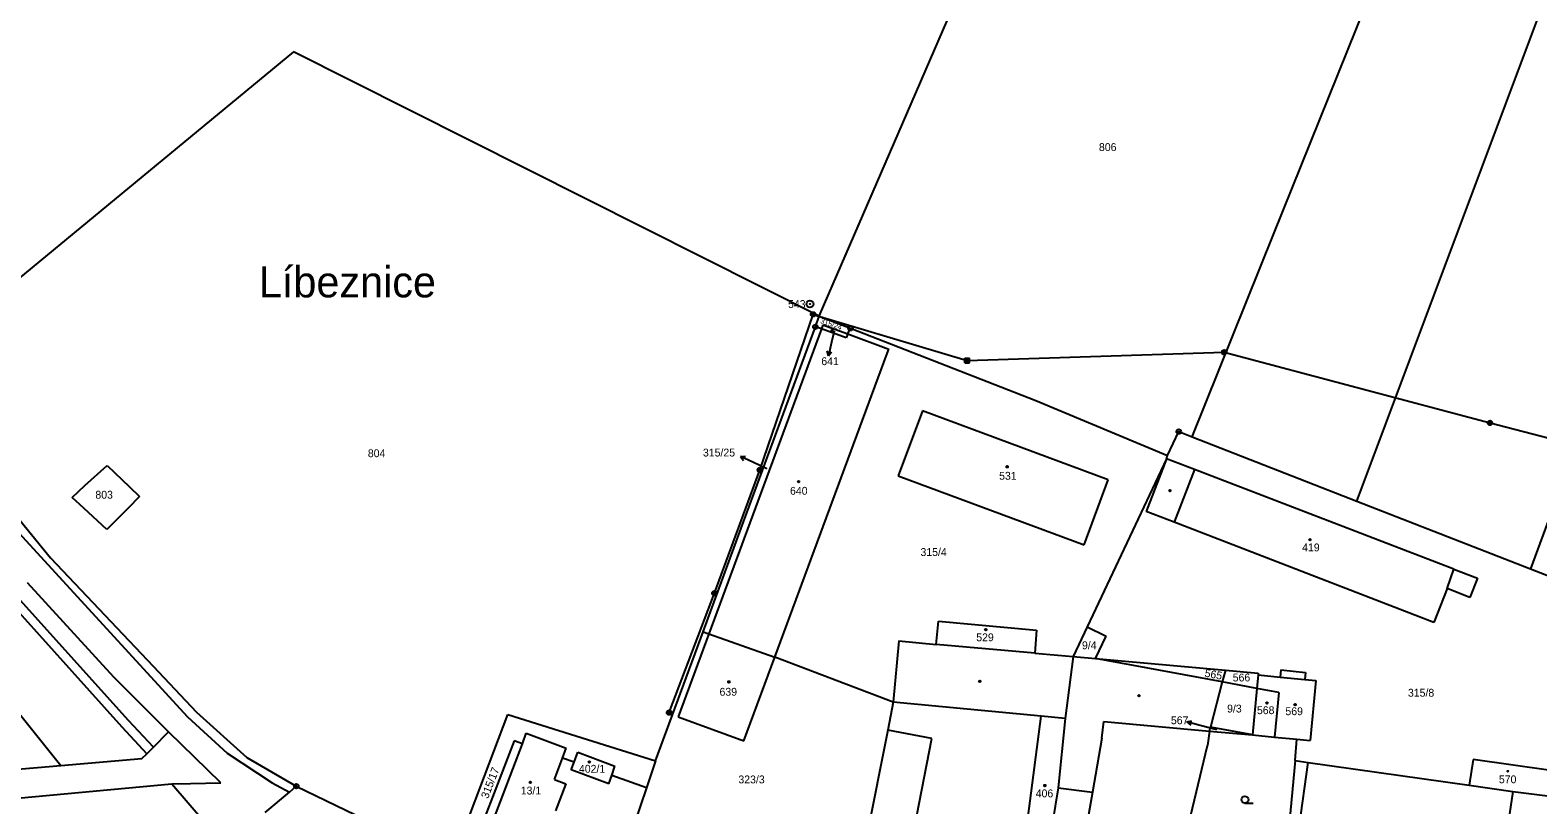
# Model space of a CAD drawing. Extents: x -738131 to -734179, y -1033447 to -1030078.
# Drawn here: x -736374.8 to -736048.4, y -1031856.8 to -1031689.1 of the extents above; entities that cross this region are included whole.
import ezdxf

# ---------------------------------------------------------------- set-up
doc = ezdxf.new("R2010")
doc.units = 0
for name, color, linetype in [('Vrstva 1', 7, 'Continuous'), ('Vrstva 2', 7, 'Continuous'), ('Vrstva 3', 7, 'Continuous'), ('Vrstva 4', 7, 'Continuous'), ('Vrstva 5', 7, 'Continuous'), ('Vrstva 6', 7, 'Continuous'), ('Vrstva 7', 7, 'Continuous'), ('Vrstva 8', 7, 'Continuous')]:
    doc.layers.add(name, color=color, linetype=linetype)

msp = doc.modelspace()

# ---------------------------------------------------------------- linework, layer by layer
at = {"layer": 'Vrstva 1'}
for points in [[(-736181.96, -1031700.18), (-736159.97, -1031649.35)], [(-736087.54, -1031791.01), (-736034.3, -1031649.01)], [(-736105.57, -1031733.34), (-736083.6, -1031678.63)], [(-736317.82, -1031693.78), (-736392.24, -1031755.11)], [(-736203.95, -1031750.98), (-736317.82, -1031693.78)], [(-736203.95, -1031750.98), (-736181.96, -1031700.18)], [(-736017.61, -1031718), (-736049.93, -1031805.67)], [(-736123.18, -1031777.12), (-736105.57, -1031733.34)], [(-736204.8, -1031753.3), (-736203.95, -1031750.98)], [(-736203.95, -1031750.98), (-736197.18, -1031753.62)], [(-736203.49, -1031753.77), (-736227.87, -1031819.76)], [(-736220.85, -1031796.87), (-736204.8, -1031753.3)], [(-736203.49, -1031753.77), (-736204.8, -1031753.3)], [(-736203.15, -1031752.84), (-736203.49, -1031753.77)], [(-736198.13, -1031755.7), (-736203.49, -1031753.77)], [(-736203.15, -1031752.84), (-736197.77, -1031754.83)], [(-736197.77, -1031754.83), (-736197.18, -1031753.62)], [(-736197.18, -1031753.62), (-736157.07, -1031769.24)], [(-736197.77, -1031754.83), (-736198.13, -1031755.7)], [(-736197.77, -1031754.83), (-736188.88, -1031758.11)], [(-736213.57, -1031824.81), (-736189.23, -1031759.06)], [(-736189.23, -1031759.06), (-736188.88, -1031758.11)], [(-736157.07, -1031769.24), (-736128.53, -1031781.14)], [(-736181.62, -1031771.49), (-736186.87, -1031785.57)], [(-736141.38, -1031786.41), (-736181.62, -1031771.49)], [(-736128.53, -1031781.14), (-736126.11, -1031775.98)], [(-736126.11, -1031775.98), (-736123.18, -1031777.12)], [(-736123.18, -1031777.12), (-736087.54, -1031791.01)], [(-736388.45, -1031781.21), (-736374.52, -1031798.29)], [(-736362.95, -1031787.68), (-736358.17, -1031783.29)], [(-736358.17, -1031783.29), (-736353.31, -1031787.93)], [(-736128.75, -1031781.88), (-736145.92, -1031818.26)], [(-736128.75, -1031781.88), (-736133.15, -1031793.29)], [(-736128.75, -1031781.88), (-736128.53, -1031781.14)], [(-736122.72, -1031784.2), (-736128.75, -1031781.88)], [(-736186.87, -1031785.57), (-736146.62, -1031800.52)], [(-736146.62, -1031800.52), (-736141.38, -1031786.41)], [(-736066.53, -1031805.76), (-736122.72, -1031784.2)], [(-736365.71, -1031790.22), (-736362.95, -1031787.68)], [(-736363.23, -1031792.53), (-736365.71, -1031790.22)], [(-736351.12, -1031790.02), (-736353.62, -1031792.55)], [(-736353.31, -1031787.93), (-736351.12, -1031790.02)], [(-736398.32, -1031791.71), (-736355, -1031839.89)], [(-736358.22, -1031797.19), (-736363.23, -1031792.53)], [(-736353.62, -1031792.55), (-736358.22, -1031797.19)], [(-736127.12, -1031795.61), (-736133.15, -1031793.29)], [(-736087.54, -1031791.01), (-736049.93, -1031805.67)], [(-736070.86, -1031817.28), (-736127.12, -1031795.61)], [(-736374.52, -1031798.29), (-736370.43, -1031803.3)], [(-736229.12, -1031819.32), (-736220.85, -1031796.87)], [(-736403.94, -1031803.64), (-736368.19, -1031848.25)], [(-736370.43, -1031803.3), (-736348.19, -1031826.79)], [(-736066.53, -1031805.76), (-736061.39, -1031807.72)], [(-736049.93, -1031805.67), (-735999.83, -1031825.19)], [(-736061.39, -1031807.72), (-736063.06, -1031811.87)], [(-736353.52, -1031838.55), (-736377.64, -1031811.73)], [(-736068.02, -1031809.95), (-736070.86, -1031817.28)], [(-736063.06, -1031811.87), (-736068.02, -1031809.95)], [(-736239.42, -1031847.27), (-736229.12, -1031819.32)], [(-736229.12, -1031819.32), (-736227.87, -1031819.76)], [(-736178.64, -1031822.07), (-736178.1, -1031817.04)], [(-736178.1, -1031817.04), (-736156.89, -1031818.93)], [(-736156.89, -1031818.93), (-736157.28, -1031823.94)], [(-736145.92, -1031818.26), (-736148.96, -1031824.69)], [(-736145.92, -1031818.26), (-736141.8, -1031820.28)], [(-736227.87, -1031819.76), (-736234.5, -1031837.69)], [(-736227.87, -1031819.76), (-736213.57, -1031824.81)], [(-736186.75, -1031821.29), (-736187.98, -1031834.57)], [(-736186.75, -1031821.29), (-736178.64, -1031822.07)], [(-736157.28, -1031823.94), (-736178.64, -1031822.07)], [(-736144.16, -1031825.1), (-736141.8, -1031820.28)], [(-736220.28, -1031842.94), (-736213.57, -1031824.81)], [(-736187.98, -1031834.57), (-736213.57, -1031824.81)], [(-736157.28, -1031823.94), (-736148.96, -1031824.69)], [(-736148.96, -1031824.69), (-736150.74, -1031838.06)], [(-736148.96, -1031824.69), (-736144.16, -1031825.1)], [(-736144.16, -1031825.1), (-736116, -1031827.61)], [(-736116.68, -1031830.18), (-736144.16, -1031825.1)], [(-736348.19, -1031826.79), (-736338.8, -1031836.68)], [(-736116, -1031827.61), (-736116.68, -1031830.18)], [(-736116, -1031827.61), (-736108.9, -1031828.24)], [(-736108.92, -1031828.63), (-736109.2, -1031831.56)], [(-736108.9, -1031828.24), (-736108.92, -1031828.63)], [(-736108.92, -1031828.63), (-736104.14, -1031829.1)], [(-736103.99, -1031827.57), (-736104.14, -1031829.1)], [(-736103.99, -1031827.57), (-736098.69, -1031828.13)], [(-736098.69, -1031828.13), (-736098.84, -1031829.62)], [(-736116.68, -1031830.18), (-736119.24, -1031839.94)], [(-736109.2, -1031831.56), (-736116.68, -1031830.18)], [(-736109.2, -1031831.56), (-736110.16, -1031841.64)], [(-736104.47, -1031832.44), (-736109.2, -1031831.56)], [(-736104.47, -1031832.44), (-736105.41, -1031842.11)], [(-736098.84, -1031829.62), (-736096.44, -1031829.86)], [(-736096.44, -1031829.86), (-736097.65, -1031842.88)], [(-736187.98, -1031834.57), (-736189.14, -1031840.58)], [(-736348.13, -1031844.29), (-736353.52, -1031838.55)], [(-736338.8, -1031836.68), (-736327.94, -1031846.53)], [(-736283.52, -1031869.25), (-736271.41, -1031837.25)], [(-736271.41, -1031837.25), (-736239.42, -1031847.27)], [(-736234.5, -1031837.69), (-736220.28, -1031842.94)], [(-736159.95, -1031868.66), (-736155.88, -1031837.6)], [(-736150.74, -1031838.06), (-736155.88, -1031837.6)], [(-736150.74, -1031838.06), (-736152.25, -1031853.12)], [(-736355, -1031839.89), (-736349.57, -1031845.76)], [(-736348.13, -1031844.29), (-736344.86, -1031840.95)], [(-736333.57, -1031852.01), (-736344.86, -1031840.95)], [(-736268.25, -1031843.55), (-736267.39, -1031841.27)], [(-736267.39, -1031841.27), (-736258.73, -1031844.48)], [(-736189.14, -1031840.58), (-736193.7, -1031863.78)], [(-736119.47, -1031840.8), (-736119.92, -1031843.95)], [(-736119.47, -1031840.8), (-736119.24, -1031839.94)], [(-736119.47, -1031840.8), (-736110.16, -1031841.64)], [(-736110.16, -1031841.64), (-736119.24, -1031839.94)], [(-736110.16, -1031841.64), (-736105.41, -1031842.11)], [(-736105.41, -1031842.11), (-736100.53, -1031842.59)], [(-736349.57, -1031845.76), (-736348.13, -1031844.29)], [(-736270, -1031842.93), (-736280.66, -1031870.46)], [(-736268.25, -1031843.55), (-736270, -1031842.93)], [(-736259.54, -1031846.65), (-736258.73, -1031844.48)], [(-736257.04, -1031847.54), (-736256.22, -1031845.34)], [(-736256.22, -1031845.34), (-736248.2, -1031848.39)], [(-736127.57, -1031875.87), (-736119.92, -1031843.95)], [(-736100.91, -1031847.16), (-736100.53, -1031842.59)], [(-736100.53, -1031842.59), (-736097.65, -1031842.88)], [(-736439.15, -1031854.34), (-736368.19, -1031848.25)], [(-736368.19, -1031848.25), (-736350.62, -1031846.74)], [(-736350.62, -1031846.74), (-736349.57, -1031845.76)], [(-736327.94, -1031846.53), (-736317.19, -1031852.73)], [(-736257.04, -1031847.54), (-736259.54, -1031846.65)], [(-736257.65, -1031849.18), (-736257.04, -1031847.54)], [(-736248.9, -1031850.43), (-736248.2, -1031848.39)], [(-736239.42, -1031847.27), (-736241.39, -1031853.1)], [(-736100.91, -1031847.16), (-736102.31, -1031862.56)], [(-736100.91, -1031847.16), (-736098.07, -1031847.64)], [(-736098.07, -1031847.64), (-736063.24, -1031852.48)], [(-736062.37, -1031846.97), (-736063.24, -1031852.48)], [(-736045.56, -1031849.32), (-736062.37, -1031846.97)], [(-736423.5, -1031859.55), (-736344.17, -1031852.23)], [(-736344.17, -1031852.23), (-736340.07, -1031852.14)], [(-736344.17, -1031852.23), (-736337.08, -1031860.44)], [(-736340.07, -1031852.14), (-736333.57, -1031852.01)], [(-736249.51, -1031852.22), (-736257.65, -1031849.18)], [(-736249.51, -1031852.22), (-736248.9, -1031850.43)], [(-736241.39, -1031853.1), (-736248.9, -1031850.43)], [(-736323.92, -1031858.44), (-736318.7, -1031854.01)], [(-736318.7, -1031854.01), (-736317.19, -1031852.73)], [(-736317.19, -1031852.73), (-736287.2, -1031867.24)], [(-736241.39, -1031853.1), (-736251.44, -1031882.79)], [(-736152.25, -1031853.12), (-736154.86, -1031869.43)], [(-736063.24, -1031852.48), (-736053.78, -1031853.91)], [(-736053.78, -1031853.91), (-736046.26, -1031854.85)]]:
    msp.add_lwpolyline(points, dxfattribs=at)
at = {"layer": 'Vrstva 3'}
msp.add_line((-736111.77, -1031856.41), (-736110.02, -1031856.41), dxfattribs=at)
msp.add_circle((-736111.77, -1031855.66), 0.75, dxfattribs=at)
at = {"layer": 'Vrstva 4'}
for points in [[(-736390.93, -1031783.08), (-736340.73, -1031837.73)], [(-736122.72, -1031784.2), (-736127.12, -1031795.61)], [(-736068.02, -1031809.95), (-736066.53, -1031805.76)], [(-736356.68, -1031829.13), (-736375.37, -1031808.71)], [(-736344.86, -1031840.95), (-736356.68, -1031829.13)], [(-736104.14, -1031829.1), (-736098.84, -1031829.62)], [(-736155.88, -1031837.6), (-736187.98, -1031834.57)], [(-736340.73, -1031837.73), (-736332.19, -1031845.59)], [(-736142.74, -1031842.34), (-736142.3, -1031838.73)], [(-736142.3, -1031838.73), (-736119.47, -1031840.8)], [(-736190.89, -1031900.59), (-736179.58, -1031842.44)], [(-736179.58, -1031842.44), (-736189.14, -1031840.58)], [(-736142.74, -1031842.34), (-736144.8, -1031854.02)], [(-736332.19, -1031845.59), (-736322.39, -1031851.98)], [(-736274.46, -1031860.05), (-736268.25, -1031843.55)], [(-736261.28, -1031851.27), (-736259.54, -1031846.65)], [(-736100.07, -1031861.61), (-736098.07, -1031847.64)], [(-736322.39, -1031851.98), (-736318.7, -1031854.01)], [(-736261.28, -1031851.27), (-736258.85, -1031852.19)], [(-736258.85, -1031852.19), (-736261.05, -1031858.04)], [(-736144.8, -1031854.02), (-736155.28, -1031913.38)], [(-736152.25, -1031853.12), (-736144.8, -1031854.02)], [(-736053.78, -1031853.91), (-736055.87, -1031867.89)]]:
    msp.add_lwpolyline(points, dxfattribs=at)
at = {"layer": 'Vrstva 5'}
for centre, radius in [((-736201.13, -1031754.11), 0.175), ((-736163.26, -1031783.6), 0.175), ((-736208.4, -1031786.83), 0.175), ((-736128.02, -1031788.77), 0.175), ((-736097.68, -1031799.37), 0.175), ((-736167.9, -1031818.87), 0.175), ((-736223.52, -1031830.16), 0.175), ((-736169.19, -1031830.03), 0.175), ((-736134.71, -1031833.13), 0.175), ((-736107.01, -1031834.74), 0.175), ((-736100.91, -1031835.07), 0.175), ((-736253.76, -1031847.51), 0.175), ((-736266.53, -1031851.89), 0.175), ((-736054.85, -1031849.5), 0.117), ((-736155.11, -1031852.6), 0.175)]:
    msp.add_circle(centre, radius, dxfattribs=at)
at = {"layer": 'Vrstva 6'}
for p, q in [((-736172.41, -1031760.08), (-736171.41, -1031760.08)), ((-736172.41, -1031761.08), (-736172.41, -1031760.08)), ((-736172.41, -1031760.28), (-736171.41, -1031760.28)), ((-736172.41, -1031760.48), (-736171.41, -1031760.48)), ((-736172.41, -1031760.68), (-736171.41, -1031760.68)), ((-736172.21, -1031761.08), (-736172.21, -1031760.08)), ((-736172.01, -1031761.08), (-736172.01, -1031760.08)), ((-736171.81, -1031761.08), (-736171.81, -1031760.08)), ((-736171.61, -1031761.08), (-736171.61, -1031760.08)), ((-736171.41, -1031761.08), (-736171.41, -1031760.08)), ((-736172.41, -1031760.88), (-736171.41, -1031760.88)), ((-736172.41, -1031761.08), (-736171.41, -1031761.08))]:
    msp.add_line(p, q, dxfattribs=at)
for points in [[(-736216.8, -1031784.3), (-736205.3, -1031750.6)], [(-736205.3, -1031750.6), (-736171.91, -1031760.58)], [(-736171.91, -1031760.58), (-736116.25, -1031758.81)], [(-736116.25, -1031758.81), (-736058.71, -1031774.1)], [(-736058.71, -1031774.1), (-736001.2, -1031788.99)], [(-736226.66, -1031810.98), (-736216.8, -1031784.3)], [(-736236.48, -1031836.8), (-736226.66, -1031810.98)]]:
    msp.add_lwpolyline(points, dxfattribs=at)
for centre, radius in [((-736205.3, -1031750.6), 0.5), ((-736205.3, -1031750.6), 0.4), ((-736205.3, -1031750.6), 0.3), ((-736205.3, -1031750.6), 0.2), ((-736205.3, -1031750.6), 0.1), ((-736116.25, -1031758.81), 0.5), ((-736116.25, -1031758.81), 0.4), ((-736116.25, -1031758.81), 0.3), ((-736116.25, -1031758.81), 0.2), ((-736116.25, -1031758.81), 0.1), ((-736058.71, -1031774.1), 0.5), ((-736058.71, -1031774.1), 0.4), ((-736058.71, -1031774.1), 0.3), ((-736058.71, -1031774.1), 0.2), ((-736058.71, -1031774.1), 0.1), ((-736216.8, -1031784.3), 0.5), ((-736216.8, -1031784.3), 0.4), ((-736216.8, -1031784.3), 0.3), ((-736216.8, -1031784.3), 0.2), ((-736216.8, -1031784.3), 0.1), ((-736226.66, -1031810.98), 0.5), ((-736226.66, -1031810.98), 0.4), ((-736226.66, -1031810.98), 0.3), ((-736226.66, -1031810.98), 0.2), ((-736226.66, -1031810.98), 0.1), ((-736236.48, -1031836.8), 0.5), ((-736236.48, -1031836.8), 0.4), ((-736236.48, -1031836.8), 0.3), ((-736236.48, -1031836.8), 0.2), ((-736236.48, -1031836.8), 0.1)]:
    msp.add_circle(centre, radius, dxfattribs=at)
at = {"layer": 'Vrstva 7'}
for p, q in [((-736201.31, -1031756.64), (-736201.98, -1031759.56)), ((-736201.98, -1031759.56), (-736202.25, -1031758.48)), ((-736201.98, -1031759.56), (-736201.27, -1031758.7)), ((-736221.03, -1031781.37), (-736219.91, -1031781.33)), ((-736218.31, -1031782.63), (-736221.03, -1031781.37)), ((-736221.03, -1031781.37), (-736220.33, -1031782.24)), ((-736124.35, -1031838.79), (-736123.25, -1031838.57)), ((-736121.45, -1031839.57), (-736124.35, -1031838.79)), ((-736124.35, -1031838.79), (-736123.51, -1031839.54))]:
    msp.add_line(p, q, dxfattribs=at)
for points in [[(-736200.75, -1031754.22), (-736201.31, -1031756.64)], [(-736215.28, -1031784.04), (-736218.31, -1031782.63)], [(-736117.86, -1031840.53), (-736121.45, -1031839.57)]]:
    msp.add_lwpolyline(points, dxfattribs=at)
at = {"layer": 'Vrstva 8'}
for centre, radius in [((-736205.98, -1031748.38), 0.75), ((-736205.98, -1031748.38), 0.03), ((-736204.8, -1031753.3), 0.5), ((-736204.8, -1031753.3), 0.5), ((-736204.8, -1031753.3), 0.0303), ((-736204.8, -1031753.3), 0.0303), ((-736197.18, -1031753.62), 0.5), ((-736197.18, -1031753.62), 0.5), ((-736197.18, -1031753.62), 0.0303), ((-736197.18, -1031753.62), 0.0303), ((-736126.11, -1031775.98), 0.5), ((-736126.11, -1031775.98), 0.5), ((-736126.11, -1031775.98), 0.0303), ((-736126.11, -1031775.98), 0.0303), ((-736317.19, -1031852.73), 0.5), ((-736317.19, -1031852.73), 0.5), ((-736317.19, -1031852.73), 0.0303), ((-736317.19, -1031852.73), 0.0303)]:
    msp.add_circle(centre, radius, dxfattribs=at)

# ---------------------------------------------------------------- texts
at = {"layer": 'Vrstva 2'}
for s, height, p in [('806', 1.7, (-736143.39, -1031715.25)), ('641', 0.1, (-736200.83, -1031754.22)), ('804', 1.7, (-736301.7, -1031781.52)), ('315/25', 0.1, (-736215.49, -1031784.04)), ('531', 1.7, (-736165.01, -1031786.4)), ('803', 1.7, (-736360.7, -1031790.5)), ('640', 1.7, (-736210.28, -1031789.65)), ('315/4', 1.7, (-736182.04, -1031802.91)), ('419', 1.7, (-736099.39, -1031801.9)), ('529', 1.7, (-736169.96, -1031821.36)), ('9/4', 1.7, (-736147.07, -1031823.09)), ('566', 1.7, (-736114.42, -1031830.06)), ('639', 1.7, (-736225.55, -1031833.15)), ('315/8', 1.7, (-736076.48, -1031833.36)), ('9/3', 1.7, (-736115.64, -1031836.78)), ('568', 1.7, (-736109.18, -1031837.14)), ('569', 1.7, (-736103.01, -1031837.36)), ('567', 0.1, (-736117.96, -1031840.53)), ('402/1', 1.7, (-736255.99, -1031849.82)), ('323/3', 1.7, (-736221.46, -1031852.12)), ('570', 1.7, (-736056.79, -1031852.1)), ('13/1', 1.7, (-736268.59, -1031854.53)), ('406', 1.7, (-736157.08, -1031855.14))]:
    msp.add_text(s, height=height, dxfattribs=at).set_placement(p)
for s, height, rotation, p in [('315/24', 1.14, 340.821, (-736203.83, -1031752.46)), ('565', 1.7, 349.691, (-736120.6, -1031829.03)), ('315/17', 1.7, 69.0812, (-736275.68, -1031855.56))]:
    msp.add_text(s, height=height, rotation=rotation, dxfattribs=at).set_placement(p)
at = {"layer": 'Vrstva 7'}
for s, height, p in [('Líbeznice', 6.7, (-736325.3, -1031746.93)), ('641', 1.7, (-736203.51, -1031761.59)), ('315/25', 1.7, (-736229.14, -1031781.37)), ('567', 1.7, (-736127.81, -1031839.32))]:
    msp.add_text(s, height=height, dxfattribs=at).set_placement(p)
at = {"layer": 'Vrstva 8'}
msp.add_text('543', height=1.7, dxfattribs=at).set_placement((-736210.71, -1031749.23))

doc.saveas('drawing.dxf')
